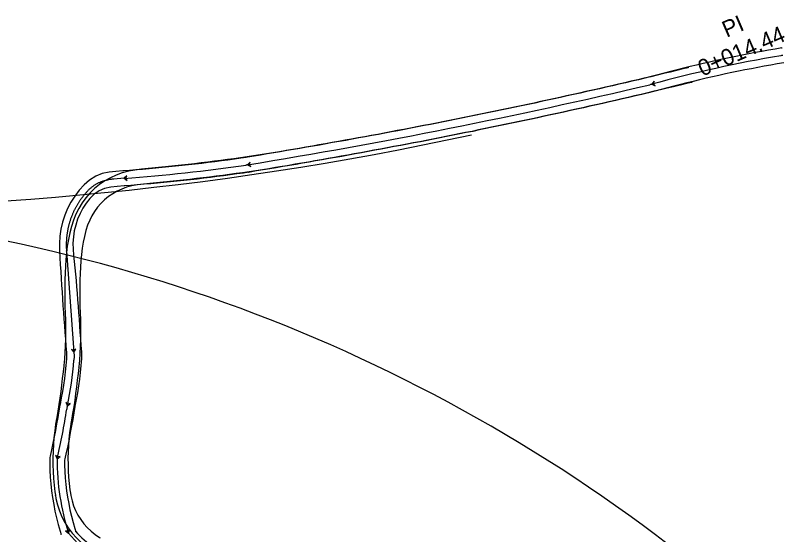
# Model space of a CAD drawing. Extents: x 0 to 513042, y 0 to 6212511.
# Drawn here: x 511633.9 to 511751.4, y 6211719.4 to 6211798.8 of the extents above; entities that cross this region are included whole.
import ezdxf

# ---------------------------------------------------------------- set-up
doc = ezdxf.new("R2010")
doc.units = 0
for name, color, linetype in [('Default', 7, 'Continuous'), ('TV_G_KRN_CL---', 7, 'Continuous'), ('TV_L_---_CL---_C', 7, 'Continuous'), ('TV_L_HOR_Cardn_T', 7, 'Continuous')]:
    doc.layers.add(name, color=color, linetype=linetype)

msp = doc.modelspace()

# ---------------------------------------------------------------- linework, layer by layer
at = {"layer": 'Default'}
for p, q in [((511650.49, 6211773.9), (511648.93, 6211773.79)), ((511641.69, 6211762.79), (511642.82, 6211747.32))]:
    msp.add_line(p, q, dxfattribs=at)
for points in [[(511750.98, 6211793.82), (511749.97, 6211793.66), (511748.96, 6211793.48), (511747.96, 6211793.3), (511746.95, 6211793.11), (511745.95, 6211792.92), (511744.95, 6211792.72), (511743.95, 6211792.52), (511742.95, 6211792.32), (511741.95, 6211792.1), (511740.95, 6211791.89), (511739.96, 6211791.67), (511738.96, 6211791.44), (511737.97, 6211791.21), (511736.97, 6211790.97), (511735.98, 6211790.73), (511734.99, 6211790.48), (511734, 6211790.23), (511733.01, 6211789.98), (511732.03, 6211789.71), (511731.04, 6211789.45), (511730.84, 6211789.39)], [(511751.14, 6211792.68), (511751.04, 6211792.67), (511750.94, 6211792.65), (511750.84, 6211792.64)], [(511751.3, 6211791.54), (511750.31, 6211791.38), (511749.31, 6211791.21), (511748.32, 6211791.03), (511747.33, 6211790.84), (511746.34, 6211790.65), (511745.35, 6211790.46), (511744.36, 6211790.26), (511743.37, 6211790.06), (511742.38, 6211789.85), (511741.39, 6211789.63), (511740.41, 6211789.41), (511739.42, 6211789.19), (511738.44, 6211788.96), (511737.46, 6211788.72), (511736.48, 6211788.48), (511735.5, 6211788.24), (511734.52, 6211787.99), (511733.55, 6211787.74), (511732.57, 6211787.48), (511731.6, 6211787.22), (511731.4, 6211787.16)], [(511736.68, 6211790.81), (511735.89, 6211790.62), (511734.91, 6211790.38), (511733.92, 6211790.14), (511732.93, 6211789.9), (511731.94, 6211789.67), (511730.96, 6211789.43), (511729.97, 6211789.2), (511728.98, 6211788.97), (511727.99, 6211788.74), (511727, 6211788.51), (511726.02, 6211788.28), (511725.03, 6211788.05), (511724.04, 6211787.83), (511723.05, 6211787.6), (511722.06, 6211787.38), (511721.07, 6211787.15), (511720.08, 6211786.93), (511719.09, 6211786.71), (511718.09, 6211786.49), (511717.1, 6211786.27), (511716.11, 6211786.06), (511715.12, 6211785.84), (511714.13, 6211785.63), (511713.14, 6211785.41), (511712.14, 6211785.2), (511711.15, 6211784.99), (511710.16, 6211784.78), (511709.16, 6211784.57), (511708.17, 6211784.36), (511707.18, 6211784.15), (511706.18, 6211783.95), (511705.19, 6211783.74), (511704.19, 6211783.54), (511703.2, 6211783.34), (511702.2, 6211783.14), (511701.21, 6211782.94), (511700.21, 6211782.74), (511699.22, 6211782.54), (511698.22, 6211782.34), (511697.23, 6211782.15), (511696.23, 6211781.95), (511695.23, 6211781.76), (511694.24, 6211781.57), (511693.24, 6211781.38), (511692.24, 6211781.19), (511691.25, 6211781), (511690.25, 6211780.81), (511689.25, 6211780.62), (511688.25, 6211780.44), (511687.26, 6211780.25), (511686.26, 6211780.07), (511685.26, 6211779.89), (511684.26, 6211779.71), (511683.26, 6211779.53), (511682.26, 6211779.35), (511681.26, 6211779.17), (511680.26, 6211779), (511679.26, 6211778.82), (511678.26, 6211778.65), (511677.26, 6211778.48), (511676.26, 6211778.3), (511675.26, 6211778.13), (511675.06, 6211778.1)], [(511730.84, 6211789.39), (511730.06, 6211789.2), (511729.08, 6211788.97), (511728.09, 6211788.74), (511727.1, 6211788.51), (511726.11, 6211788.28), (511725.12, 6211788.05), (511724.13, 6211787.83), (511723.14, 6211787.6), (511722.15, 6211787.38), (511721.16, 6211787.15), (511720.17, 6211786.93), (511719.18, 6211786.71), (511718.19, 6211786.49), (511717.2, 6211786.27), (511716.21, 6211786.06), (511715.21, 6211785.84), (511714.22, 6211785.63), (511713.23, 6211785.41), (511712.24, 6211785.2), (511711.24, 6211784.99), (511710.25, 6211784.78), (511709.26, 6211784.57), (511708.26, 6211784.36), (511707.27, 6211784.15), (511706.28, 6211783.95), (511705.28, 6211783.74), (511704.29, 6211783.54), (511703.29, 6211783.34), (511702.3, 6211783.13), (511701.3, 6211782.93), (511700.31, 6211782.73), (511699.31, 6211782.54), (511698.32, 6211782.34), (511697.32, 6211782.14), (511696.33, 6211781.95), (511695.33, 6211781.76), (511694.33, 6211781.56), (511693.34, 6211781.37), (511692.34, 6211781.18), (511691.34, 6211780.99), (511690.34, 6211780.81), (511689.35, 6211780.62), (511688.35, 6211780.43), (511687.35, 6211780.25), (511686.35, 6211780.07), (511685.35, 6211779.89), (511684.35, 6211779.7), (511683.35, 6211779.52), (511682.36, 6211779.35), (511681.36, 6211779.17), (511680.36, 6211778.99), (511679.36, 6211778.82), (511678.36, 6211778.64), (511677.36, 6211778.47), (511676.36, 6211778.3), (511675.36, 6211778.13), (511674.35, 6211777.96), (511673.35, 6211777.79), (511672.35, 6211777.62), (511671.35, 6211777.46), (511670.35, 6211777.29), (511669.35, 6211777.13), (511669.15, 6211777.1)], [(511731.12, 6211788.28), (511731.66, 6211788.06), (511731.4, 6211788.35), (511731.47, 6211788.74), (511731.12, 6211788.28)], [(511737.22, 6211788.57), (511736.44, 6211788.38), (511735.45, 6211788.14), (511734.46, 6211787.9), (511733.47, 6211787.67), (511732.48, 6211787.43), (511731.49, 6211787.2), (511730.5, 6211786.96), (511729.51, 6211786.73), (511728.51, 6211786.5), (511727.52, 6211786.27), (511726.53, 6211786.04), (511725.54, 6211785.81), (511724.55, 6211785.58), (511723.56, 6211785.36), (511722.56, 6211785.13), (511721.57, 6211784.91), (511720.58, 6211784.69), (511719.58, 6211784.47), (511718.59, 6211784.25), (511717.6, 6211784.03), (511716.6, 6211783.81), (511715.61, 6211783.59), (511714.61, 6211783.38), (511713.62, 6211783.16), (511712.62, 6211782.95), (511711.63, 6211782.74), (511710.63, 6211782.53), (511709.64, 6211782.32), (511708.64, 6211782.11), (511707.64, 6211781.9), (511706.65, 6211781.7), (511705.65, 6211781.49), (511704.65, 6211781.29), (511703.66, 6211781.08), (511702.66, 6211780.88), (511701.66, 6211780.68), (511700.66, 6211780.48), (511699.67, 6211780.28), (511698.67, 6211780.09), (511697.67, 6211779.89), (511696.67, 6211779.69), (511695.67, 6211779.5), (511694.67, 6211779.31), (511693.67, 6211779.12), (511692.67, 6211778.93), (511691.67, 6211778.74), (511690.67, 6211778.55), (511689.67, 6211778.36), (511688.67, 6211778.18), (511687.67, 6211777.99), (511686.67, 6211777.81), (511685.67, 6211777.63), (511684.67, 6211777.45), (511683.67, 6211777.27), (511682.66, 6211777.09), (511681.66, 6211776.91), (511680.66, 6211776.73), (511679.66, 6211776.56), (511678.66, 6211776.38), (511677.65, 6211776.21), (511676.65, 6211776.04), (511675.65, 6211775.87), (511675.45, 6211775.83)], [(511731.12, 6211788.28), (511731.02, 6211788.25), (511730.93, 6211788.22), (511730.83, 6211788.2)], [(511731.4, 6211787.16), (511730.6, 6211786.97), (511729.61, 6211786.73), (511728.62, 6211786.5), (511727.63, 6211786.27), (511726.64, 6211786.04), (511725.65, 6211785.81), (511724.65, 6211785.59), (511723.66, 6211785.36), (511722.67, 6211785.14), (511721.68, 6211784.91), (511720.68, 6211784.69), (511719.69, 6211784.47), (511718.7, 6211784.25), (511717.7, 6211784.03), (511716.71, 6211783.81), (511715.71, 6211783.6), (511714.72, 6211783.38), (511713.73, 6211783.17), (511712.73, 6211782.95), (511711.73, 6211782.74), (511710.74, 6211782.53), (511709.74, 6211782.32), (511708.75, 6211782.11), (511707.75, 6211781.9), (511706.75, 6211781.7), (511705.76, 6211781.49), (511704.76, 6211781.29), (511703.76, 6211781.08), (511702.77, 6211780.88), (511701.77, 6211780.68), (511700.77, 6211780.48), (511699.77, 6211780.28), (511698.77, 6211780.09), (511697.78, 6211779.89), (511696.78, 6211779.69), (511695.78, 6211779.5), (511694.78, 6211779.31), (511693.78, 6211779.12), (511692.78, 6211778.93), (511691.78, 6211778.74), (511690.78, 6211778.55), (511689.78, 6211778.36), (511688.78, 6211778.18), (511687.78, 6211777.99), (511686.78, 6211777.81), (511685.78, 6211777.62), (511684.77, 6211777.44), (511683.77, 6211777.26), (511682.77, 6211777.08), (511681.77, 6211776.91), (511680.77, 6211776.73), (511679.76, 6211776.55), (511678.76, 6211776.38), (511677.76, 6211776.21), (511676.76, 6211776.03), (511675.75, 6211775.86), (511674.75, 6211775.69), (511673.75, 6211775.52), (511672.74, 6211775.36), (511671.74, 6211775.19), (511670.73, 6211775.03), (511669.73, 6211774.86), (511669.53, 6211774.83)], [(511669.15, 6211777.1), (511668.35, 6211776.98), (511667.35, 6211776.84), (511666.35, 6211776.7), (511665.35, 6211776.57), (511664.35, 6211776.44), (511663.35, 6211776.31), (511662.35, 6211776.19), (511661.34, 6211776.07), (511660.34, 6211775.96), (511659.34, 6211775.85), (511658.33, 6211775.74), (511657.33, 6211775.64), (511656.32, 6211775.54), (511655.32, 6211775.45), (511654.31, 6211775.36), (511653.31, 6211775.27), (511652.3, 6211775.19), (511651.29, 6211775.11), (511650.39, 6211775.05)], [(511675.06, 6211778.1), (511674.26, 6211777.97), (511673.27, 6211777.8), (511672.27, 6211777.64), (511671.27, 6211777.49), (511670.28, 6211777.33), (511669.28, 6211777.18), (511668.28, 6211777.04), (511667.28, 6211776.9), (511666.28, 6211776.76), (511665.28, 6211776.63), (511664.28, 6211776.5), (511663.28, 6211776.38), (511662.27, 6211776.25), (511661.27, 6211776.14), (511660.27, 6211776.02), (511659.27, 6211775.91), (511658.26, 6211775.81), (511657.26, 6211775.71), (511656.35, 6211775.62)], [(511675.45, 6211775.83), (511674.64, 6211775.7), (511673.64, 6211775.53), (511672.63, 6211775.37), (511671.63, 6211775.21), (511670.62, 6211775.06), (511669.61, 6211774.91), (511668.6, 6211774.76), (511667.6, 6211774.62), (511666.59, 6211774.48), (511665.58, 6211774.35), (511664.57, 6211774.22), (511663.56, 6211774.09), (511662.55, 6211773.97), (511661.54, 6211773.85), (511660.52, 6211773.74), (511659.51, 6211773.63), (511658.5, 6211773.52), (511657.49, 6211773.42), (511656.57, 6211773.33)], [(511669.34, 6211775.96), (511669.24, 6211775.95), (511669.14, 6211775.93)], [(511669.34, 6211775.96), (511669.84, 6211775.69), (511669.62, 6211776.01), (511669.73, 6211776.38), (511669.34, 6211775.96)], [(511650.39, 6211775.05), (511650.28, 6211775.04), (511649.25, 6211774.96), (511648.2, 6211774.86), (511647.16, 6211774.62), (511646.15, 6211774.21), (511645.2, 6211773.63), (511644.37, 6211772.88), (511643.63, 6211772.07), (511642.96, 6211771.19), (511642.36, 6211770.26), (511641.85, 6211769.28), (511641.43, 6211768.26), (511641.09, 6211767.21), (511640.84, 6211766.14), (511640.68, 6211765.05), (511640.62, 6211763.94), (511640.64, 6211762.85), (511640.69, 6211761.77), (511640.74, 6211760.71), (511640.81, 6211759.65), (511640.87, 6211758.59), (511640.94, 6211757.55), (511641.01, 6211756.5), (511641.08, 6211755.47), (511641.15, 6211754.43), (511641.23, 6211753.4), (511641.3, 6211752.38), (511641.37, 6211751.35), (511641.45, 6211750.33), (511641.52, 6211749.31), (511641.59, 6211748.29), (511641.67, 6211747.27)], [(511656.35, 6211775.62), (511656.25, 6211775.61), (511655.22, 6211775.51), (511654.19, 6211775.42), (511653.17, 6211775.31), (511652.15, 6211775.17), (511651.15, 6211774.98), (511650.2, 6211774.73), (511649.28, 6211774.39), (511648.4, 6211773.99), (511647.55, 6211773.51), (511646.75, 6211772.95), (511645.99, 6211772.34), (511645.29, 6211771.66), (511644.65, 6211770.92), (511644.08, 6211770.14), (511643.57, 6211769.3), (511643.13, 6211768.43), (511642.76, 6211767.51), (511642.45, 6211766.55), (511642.19, 6211765.56), (511641.98, 6211764.55), (511641.81, 6211763.54), (511641.68, 6211762.51), (511641.58, 6211761.48), (511641.51, 6211760.46), (511641.46, 6211759.43), (511641.43, 6211758.4), (511641.42, 6211757.37), (511641.42, 6211756.35), (511641.43, 6211755.32), (511641.45, 6211754.3), (511641.48, 6211753.28)], [(511669.53, 6211774.83), (511668.72, 6211774.71), (511667.71, 6211774.57), (511666.7, 6211774.43), (511665.69, 6211774.29), (511664.68, 6211774.16), (511663.67, 6211774.04), (511662.66, 6211773.91), (511661.65, 6211773.79), (511660.64, 6211773.68), (511659.62, 6211773.57), (511658.61, 6211773.46), (511657.6, 6211773.36), (511656.58, 6211773.26), (511655.57, 6211773.16), (511654.56, 6211773.07), (511653.54, 6211772.99), (511652.53, 6211772.9), (511651.51, 6211772.82), (511650.6, 6211772.75)], [(511648.93, 6211773.79), (511648.83, 6211773.78), (511648.73, 6211773.77), (511648.63, 6211773.76), (511648.53, 6211773.74), (511648.43, 6211773.73), (511648.33, 6211773.71), (511648.23, 6211773.7), (511648.13, 6211773.68), (511648.03, 6211773.66), (511647.93, 6211773.64), (511647.83, 6211773.62), (511647.73, 6211773.59), (511647.63, 6211773.57), (511647.53, 6211773.54), (511647.44, 6211773.51), (511647.34, 6211773.48), (511647.24, 6211773.45), (511647.15, 6211773.42), (511647.05, 6211773.38), (511646.96, 6211773.35), (511646.86, 6211773.31), (511646.77, 6211773.27), (511646.67, 6211773.23), (511646.58, 6211773.19), (511646.49, 6211773.14), (511646.4, 6211773.1), (511646.31, 6211773.05), (511646.22, 6211773), (511646.13, 6211772.95), (511646.05, 6211772.9), (511645.96, 6211772.84), (511645.88, 6211772.79), (511645.79, 6211772.73), (511645.71, 6211772.67), (511645.63, 6211772.61), (511645.55, 6211772.55), (511645.47, 6211772.49), (511645.39, 6211772.42), (511645.31, 6211772.35), (511645.24, 6211772.29), (511645.16, 6211772.22), (511645.09, 6211772.14), (511645.02, 6211772.07), (511644.95, 6211772), (511644.88, 6211771.92), (511644.81, 6211771.85), (511644.74, 6211771.77), (511644.68, 6211771.7), (511644.61, 6211771.62), (511644.54, 6211771.55), (511644.48, 6211771.47), (511644.41, 6211771.39), (511644.35, 6211771.31), (511644.28, 6211771.23), (511644.22, 6211771.15), (511644.16, 6211771.07), (511644.1, 6211770.99), (511644.03, 6211770.91), (511643.97, 6211770.83), (511643.91, 6211770.75), (511643.85, 6211770.66), (511643.8, 6211770.58), (511643.74, 6211770.5), (511643.68, 6211770.41), (511643.63, 6211770.33), (511643.57, 6211770.24), (511643.52, 6211770.16), (511643.46, 6211770.07), (511643.41, 6211769.99), (511643.36, 6211769.9), (511643.3, 6211769.81), (511643.25, 6211769.72), (511643.2, 6211769.64), (511643.15, 6211769.55), (511643.1, 6211769.46), (511643.06, 6211769.37), (511643.01, 6211769.28), (511642.96, 6211769.19), (511642.92, 6211769.1), (511642.87, 6211769.01), (511642.83, 6211768.91), (511642.78, 6211768.82), (511642.74, 6211768.73), (511642.7, 6211768.64), (511642.66, 6211768.55), (511642.62, 6211768.45), (511642.58, 6211768.36), (511642.54, 6211768.26), (511642.5, 6211768.17), (511642.46, 6211768.08), (511642.43, 6211767.98), (511642.39, 6211767.89), (511642.36, 6211767.79), (511642.32, 6211767.69), (511642.29, 6211767.6), (511642.26, 6211767.5), (511642.23, 6211767.41), (511642.2, 6211767.31), (511642.17, 6211767.21), (511642.14, 6211767.11), (511642.11, 6211767.02), (511642.08, 6211766.92), (511642.06, 6211766.82), (511642.03, 6211766.72), (511642, 6211766.62), (511641.98, 6211766.53), (511641.96, 6211766.43), (511641.93, 6211766.33), (511641.91, 6211766.23), (511641.89, 6211766.13), (511641.87, 6211766.03), (511641.85, 6211765.93), (511641.84, 6211765.83), (511641.82, 6211765.73), (511641.8, 6211765.63), (511641.79, 6211765.53), (511641.77, 6211765.43), (511641.76, 6211765.33), (511641.74, 6211765.23), (511641.73, 6211765.13), (511641.72, 6211765.02), (511641.71, 6211764.92), (511641.7, 6211764.82), (511641.69, 6211764.72), (511641.68, 6211764.62), (511641.68, 6211764.52), (511641.67, 6211764.42), (511641.67, 6211764.32), (511641.66, 6211764.21), (511641.66, 6211764.11), (511641.65, 6211764.01), (511641.65, 6211763.91), (511641.65, 6211763.81), (511641.65, 6211763.71), (511641.65, 6211763.6), (511641.65, 6211763.5), (511641.66, 6211763.4), (511641.66, 6211763.3), (511641.66, 6211763.2), (511641.67, 6211763.1), (511641.67, 6211763), (511641.68, 6211762.89), (511641.69, 6211762.79)], [(511650.49, 6211773.9), (511650.97, 6211773.58), (511650.78, 6211773.92), (511650.92, 6211774.28), (511650.49, 6211773.9)], [(511650.6, 6211772.75), (511650.49, 6211772.75), (511649.45, 6211772.67), (511648.45, 6211772.57), (511647.52, 6211772.35), (511646.66, 6211771.99), (511645.9, 6211771.48), (511645.27, 6211770.83), (511644.7, 6211770.09), (511644.19, 6211769.32), (511643.76, 6211768.5), (511643.39, 6211767.64), (511643.1, 6211766.76), (511642.88, 6211765.86), (511642.74, 6211764.94), (511642.67, 6211764.01), (511642.69, 6211763.08), (511642.78, 6211762.15), (511642.88, 6211761.2), (511642.97, 6211760.24), (511643.06, 6211759.27), (511643.14, 6211758.3), (511643.22, 6211757.32), (511643.3, 6211756.34), (511643.37, 6211755.35), (511643.45, 6211754.36), (511643.52, 6211753.37), (511643.6, 6211752.37), (511643.67, 6211751.38), (511643.74, 6211750.38), (511643.82, 6211749.37), (511643.89, 6211748.37), (511643.97, 6211747.36)], [(511656.57, 6211773.33), (511656.47, 6211773.32), (511655.43, 6211773.22), (511654.41, 6211773.13), (511653.43, 6211773.03), (511652.51, 6211772.9), (511651.65, 6211772.74), (511650.88, 6211772.53), (511650.15, 6211772.26), (511649.44, 6211771.94), (511648.76, 6211771.55), (511648.12, 6211771.11), (511647.52, 6211770.61), (511646.96, 6211770.07), (511646.44, 6211769.48), (511645.98, 6211768.85), (511645.58, 6211768.18), (511645.23, 6211767.48), (511644.92, 6211766.72), (511644.66, 6211765.9), (511644.43, 6211765.03), (511644.24, 6211764.13), (511644.09, 6211763.2), (511643.97, 6211762.25), (511643.88, 6211761.29), (511643.81, 6211760.32), (511643.76, 6211759.34), (511643.73, 6211758.35), (511643.72, 6211757.35), (511643.72, 6211756.36), (511643.73, 6211755.36), (511643.75, 6211754.36), (511643.78, 6211753.35)], [(511641.48, 6211753.28), (511641.51, 6211752.27), (511641.53, 6211751.27), (511641.53, 6211750.27), (511641.51, 6211749.28), (511641.48, 6211748.28), (511641.43, 6211747.28), (511641.36, 6211746.29), (511641.27, 6211745.3), (511641.26, 6211745.2)], [(511643.78, 6211753.35), (511643.81, 6211752.33), (511643.83, 6211751.3), (511643.83, 6211750.26), (511643.81, 6211749.22), (511643.78, 6211748.18), (511643.72, 6211747.15), (511643.65, 6211746.11), (511643.56, 6211745.08), (511643.55, 6211744.97)], [(511642.82, 6211747.32), (511643.13, 6211747.8), (511642.8, 6211747.6), (511642.43, 6211747.75), (511642.82, 6211747.32)], [(511641.67, 6211747.27), (511641.68, 6211746.29), (511641.6, 6211745.3), (511641.49, 6211744.3), (511641.37, 6211743.31), (511641.23, 6211742.31), (511641.07, 6211741.32), (511640.89, 6211740.34), (511640.7, 6211739.35), (511640.68, 6211739.25)], [(511642.82, 6211747.32), (511642.82, 6211747.22), (511642.83, 6211747.12), (511642.84, 6211747.01), (511642.84, 6211746.91), (511642.84, 6211746.81), (511642.84, 6211746.71), (511642.84, 6211746.61), (511642.84, 6211746.51), (511642.84, 6211746.4), (511642.83, 6211746.3), (511642.83, 6211746.2), (511642.82, 6211746.1)], [(511643.97, 6211747.36), (511643.98, 6211746.32), (511643.9, 6211745.27), (511643.79, 6211744.23), (511643.67, 6211743.2), (511643.52, 6211742.16), (511643.36, 6211741.13), (511643.18, 6211740.1), (511642.98, 6211739.08), (511642.96, 6211738.98)], [(511641.26, 6211745.2), (511641.17, 6211744.3), (511641.05, 6211743.3), (511640.93, 6211742.3), (511640.8, 6211741.31), (511640.66, 6211740.31), (511640.51, 6211739.32), (511640.35, 6211738.32), (511640.19, 6211737.33), (511640.15, 6211737.13)], [(511643.55, 6211744.97), (511643.45, 6211744.05), (511643.34, 6211743.03), (511643.21, 6211742.02), (511643.08, 6211741), (511642.94, 6211739.98), (511642.79, 6211738.97), (511642.62, 6211737.95), (511642.45, 6211736.94), (511642.42, 6211736.74)], [(511641.82, 6211739.11), (511642.26, 6211739.49), (511641.88, 6211739.4), (511641.57, 6211739.63), (511641.82, 6211739.11)], [(511640.68, 6211739.25), (511640.52, 6211738.35), (511640.36, 6211737.36), (511640.18, 6211736.37), (511640, 6211735.38), (511639.8, 6211734.39), (511639.6, 6211733.4), (511639.39, 6211732.42), (511639.17, 6211731.43), (511639.13, 6211731.24)], [(511642.96, 6211738.98), (511642.81, 6211738.08), (511642.64, 6211737.06), (511642.46, 6211736.05), (511642.27, 6211735.04), (511642.08, 6211734.03), (511641.87, 6211733.02), (511641.66, 6211732.02), (511641.43, 6211731.02), (511641.39, 6211730.82)], [(511641.82, 6211739.11), (511641.8, 6211739.01), (511641.78, 6211738.92), (511641.76, 6211738.82), (511641.74, 6211738.72), (511641.73, 6211738.61)], [(511640.15, 6211737.13), (511640.02, 6211736.31), (511639.88, 6211735.29), (511639.77, 6211734.25), (511639.69, 6211733.22), (511639.64, 6211732.18), (511639.61, 6211731.15), (511639.62, 6211730.11), (511639.65, 6211729.07), (511639.72, 6211728.04), (511639.81, 6211727), (511639.93, 6211725.97), (511640, 6211725.46)], [(511642.42, 6211736.74), (511642.3, 6211735.97), (511642.17, 6211735.01), (511642.06, 6211734.04), (511641.99, 6211733.07), (511641.94, 6211732.1), (511641.91, 6211731.12), (511641.92, 6211730.15), (511641.95, 6211729.18), (511642.01, 6211728.21), (511642.1, 6211727.24), (511642.21, 6211726.27), (511642.28, 6211725.79)], [(511639.12, 6211731.18), (511639.12, 6211730.34), (511639.15, 6211729.29), (511639.21, 6211728.24), (511639.29, 6211727.19), (511639.41, 6211726.15), (511639.56, 6211725.11), (511639.73, 6211724.07), (511639.93, 6211723.04), (511640.17, 6211722.01), (511640.43, 6211720.99), (511640.72, 6211719.98), (511640.87, 6211719.48)], [(511640.26, 6211731.03), (511640.7, 6211731.39), (511640.32, 6211731.31), (511640.02, 6211731.55), (511640.26, 6211731.03)], [(511641.4, 6211730.87), (511641.4, 6211730.08), (511641.44, 6211729.09), (511641.5, 6211728.11), (511641.59, 6211727.12), (511641.7, 6211726.14), (511641.85, 6211725.17), (511642.02, 6211724.19), (511642.22, 6211723.23), (511642.45, 6211722.26), (511642.7, 6211721.31), (511642.98, 6211720.36), (511643.13, 6211719.89)], [(511640, 6211725.46), (511640.08, 6211724.97), (511640.31, 6211724.01), (511640.61, 6211723.08), (511640.99, 6211722.17), (511641.44, 6211721.29), (511641.96, 6211720.46), (511642.55, 6211719.67), (511643.2, 6211718.93), (511643.91, 6211718.25), (511644.67, 6211717.63), (511645.48, 6211717.08), (511645.65, 6211716.97)], [(511642.28, 6211725.79), (511642.35, 6211725.4), (511642.53, 6211724.62), (511642.77, 6211723.86), (511643.08, 6211723.13), (511643.44, 6211722.42), (511643.86, 6211721.75), (511644.34, 6211721.11), (511644.86, 6211720.52), (511645.44, 6211719.97), (511646.05, 6211719.47), (511646.71, 6211719.02), (511646.84, 6211718.94)], [(511642, 6211719.68), (511642.19, 6211720.23), (511641.91, 6211719.96), (511641.53, 6211720.01), (511642, 6211719.68)], [(511643.08, 6211719.97), (511643.39, 6211719.62), (511644.04, 6211718.95), (511644.74, 6211718.34), (511645.5, 6211717.78), (511646.29, 6211717.29), (511647.12, 6211716.87), (511647.99, 6211716.52), (511648.88, 6211716.24), (511649.79, 6211716.03), (511650.72, 6211715.91), (511651.65, 6211715.85), (511651.83, 6211715.85)]]:
    msp.add_lwpolyline(points, dxfattribs=at)
for points in [[(511731.12, 6211788.28), (511731.66, 6211788.06), (511731.4, 6211788.35), (511731.47, 6211788.74)], [(511669.34, 6211775.96), (511669.84, 6211775.69), (511669.62, 6211776.01), (511669.73, 6211776.38)], [(511650.49, 6211773.9), (511650.97, 6211773.58), (511650.78, 6211773.92), (511650.92, 6211774.28)], [(511642.82, 6211747.32), (511643.13, 6211747.8), (511642.8, 6211747.6), (511642.43, 6211747.75)], [(511641.82, 6211739.11), (511642.26, 6211739.49), (511641.88, 6211739.4), (511641.57, 6211739.63)], [(511640.26, 6211731.03), (511640.7, 6211731.39), (511640.32, 6211731.31), (511640.02, 6211731.55)], [(511642, 6211719.68), (511642.19, 6211720.23), (511641.91, 6211719.96), (511641.53, 6211720.01)]]:
    msp.add_lwpolyline(points, close=True, dxfattribs=at)
for centre in [(511750.98, 6211793.82), (511750.84, 6211792.64), (511750.84, 6211792.64), (511751.14, 6211792.68), (511751.3, 6211791.54), (511736.68, 6211790.81), (511736.68, 6211790.81), (511730.84, 6211789.39), (511730.84, 6211789.39), (511730.83, 6211788.2), (511730.83, 6211788.2), (511731.12, 6211788.28), (511731.12, 6211788.28), (511737.22, 6211788.57), (511737.22, 6211788.57), (511731.4, 6211787.16), (511731.4, 6211787.16), (511669.15, 6211777.1), (511669.15, 6211777.1), (511675.06, 6211778.1), (511675.06, 6211778.1), (511669.14, 6211775.93), (511669.14, 6211775.93), (511669.34, 6211775.96), (511669.34, 6211775.96), (511675.45, 6211775.83), (511675.45, 6211775.83), (511650.39, 6211775.05), (511650.39, 6211775.05), (511656.35, 6211775.62), (511656.35, 6211775.62), (511669.53, 6211774.83), (511669.53, 6211774.83), (511648.93, 6211773.79), (511648.93, 6211773.79), (511650.49, 6211773.9), (511650.49, 6211773.9), (511650.6, 6211772.75), (511650.6, 6211772.75), (511656.57, 6211773.33), (511656.57, 6211773.33), (511641.69, 6211762.79), (511641.69, 6211762.79), (511641.48, 6211753.28), (511641.48, 6211753.28), (511643.78, 6211753.35), (511643.78, 6211753.35), (511641.67, 6211747.27), (511641.67, 6211747.27), (511642.82, 6211747.32), (511642.82, 6211747.32), (511643.97, 6211747.36), (511643.97, 6211747.36), (511642.82, 6211746.1), (511642.82, 6211746.1), (511641.26, 6211745.2), (511641.26, 6211745.2), (511643.55, 6211744.97), (511643.55, 6211744.97), (511640.68, 6211739.25), (511640.68, 6211739.25), (511641.73, 6211738.61), (511641.73, 6211738.61), (511641.82, 6211739.11), (511641.82, 6211739.11), (511642.96, 6211738.98), (511642.96, 6211738.98), (511640.15, 6211737.13), (511640.15, 6211737.13), (511642.42, 6211736.74), (511642.42, 6211736.74), (511639.12, 6211731.18), (511639.13, 6211731.24), (511640.26, 6211731.03), (511640.26, 6211731.03), (511641.4, 6211730.87), (511641.39, 6211730.82), (511640, 6211725.46), (511640, 6211725.46), (511642.28, 6211725.79), (511642.28, 6211725.79), (511640.87, 6211719.48), (511642, 6211719.68), (511642, 6211719.68), (511643.08, 6211719.97), (511643.13, 6211719.89)]:
    msp.add_circle(centre, 0.0127, dxfattribs=at)
for centre, radius, start, end in [((511784.44, 6211594), 201.46, 99.6006, 105.3456), ((511526.89, 6212652.34), 887.87, 279.23237, 283.27907), ((511631.57, 6212034.06), 260.85, 274.1588, 278.2793), ((511586.12, 6211750.65), 56.88, 348.3033, 355.4162), ((511529.3, 6211756.45), 113.84, 347.0954, 350.9867), ((511676.58, 6211730.8), 36.32, 179.6455, 197.824), ((511651.82, 6211727.17), 12.35, 217.3209, 267.9025)]:
    msp.add_arc(centre, radius, start, end, dxfattribs=at)
at = {"layer": 'TV_G_KRN_CL---'}
msp.add_arc((511599.35, 6212259.35), 490, 254.007, 282.2807, dxfattribs=at)
at = {"layer": 'TV_L_---_CL---_C'}
msp.add_arc((511581.47, 6211519.57), 250, 51.9142, 88.6158, dxfattribs=at)

# ---------------------------------------------------------------- texts
at = {"layer": 'TV_L_HOR_Cardn_T'}
for s, p in [('PI', (511742.55, 6211795.38)), ('0+014.44', (511738.85, 6211789.43))]:
    msp.add_text(s, height=2.5, rotation=23.2934, dxfattribs=at).set_placement(p)

doc.saveas('drawing.dxf')
